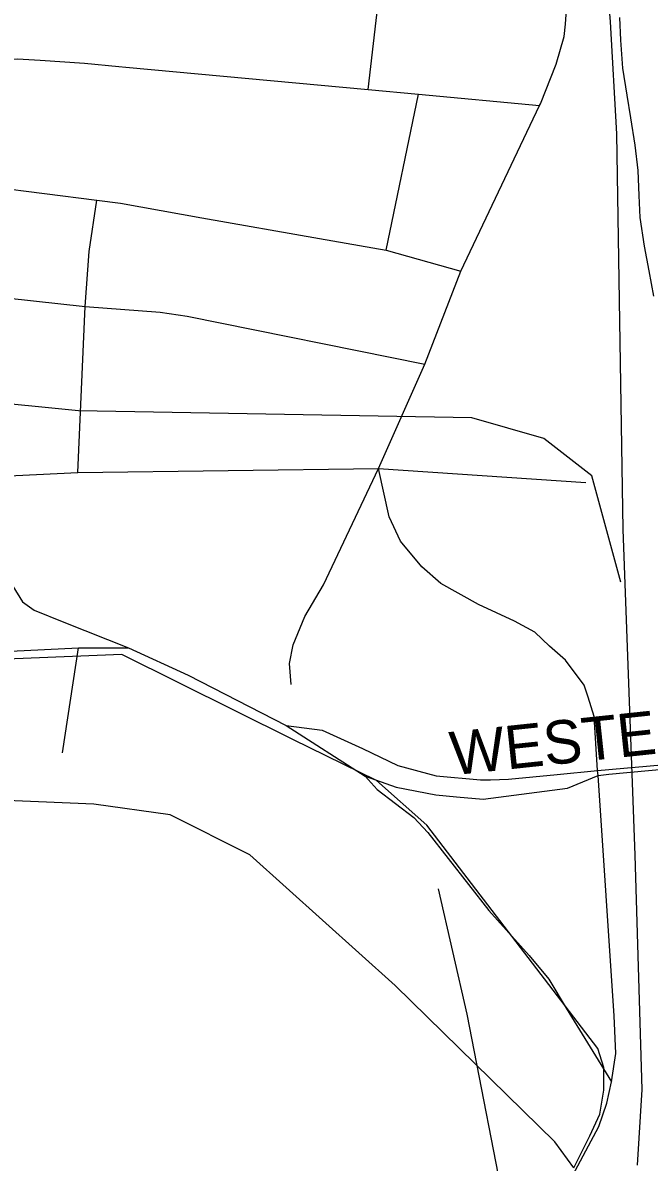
# Model space of a CAD drawing. Extents: x -8.2 to 38.5, y -0.1 to 21.9.
# Drawn here: x 5.1615 to 5.4346, y 15.5938 to 16.091 of the extents above; entities that cross this region are included whole.
import ezdxf

# ---------------------------------------------------------------- set-up
doc = ezdxf.new("R2010")
doc.units = 0
for name, color, linetype in [('GM_X_Major_Lake', 7, 'Continuous'), ('GM_X_Minor_River', 7, 'Continuous'), ('GM_X_Township_Subdivision_Text', 7, 'Continuous'), ('GM_X_Township_Text', 7, 'Continuous'), ('GM_X_US_Location', 7, 'Continuous')]:
    doc.layers.add(name, color=color, linetype=linetype)

msp = doc.modelspace()

# ---------------------------------------------------------------- linework, layer by layer
at = {"layer": 'GM_X_Minor_River'}
msp.add_lwpolyline([(5.42167, 16.09329), (5.42215, 16.0834), (5.42295, 16.07123), (5.42489, 16.0594), (5.42651, 16.04949), (5.42845, 16.03766), (5.42966, 16.02662), (5.43011, 16.01559), (5.4306, 16.00608), (5.43252, 15.9935), (5.43449, 15.98281), (5.43646, 15.97175)], dxfattribs=at)
at = {"layer": 'GM_X_Township_Subdivision_Text'}
for p, q in [((5.31215, 16.06186), (5.31772, 16.11078)), ((5.31993, 15.99183), (5.33406, 16.05983)), ((5.31655, 15.89649), (5.40697, 15.89045)), ((5.17882, 15.77245), (5.18572, 15.81826))]:
    msp.add_line(p, q, dxfattribs=at)
for points in [[(4.99245, 16.10244), (5.01831, 16.09032), (5.02882, 16.08584), (5.04124, 16.08207), (5.05714, 16.08011), (5.11356, 16.07434), (5.12607, 16.07361), (5.13747, 16.07405), (5.15915, 16.07534), (5.169, 16.07469), (5.18833, 16.07338), (5.20337, 16.07199)], [(5.20337, 16.07199), (5.20638, 16.07171), (5.31215, 16.06186), (5.33406, 16.05983), (5.38685, 16.05491)], [(4.96834, 16.04118), (5.00922, 16.03624), (5.03609, 16.03307), (5.10232, 16.02526), (5.19371, 16.01366), (5.20406, 16.01226), (5.21295, 16.01065)], [(5.18541, 15.89482), (5.18867, 15.9672), (5.19035, 15.99127), (5.19371, 16.01366)], [(5.21295, 16.01065), (5.23961, 16.00583), (5.2909, 15.99689)], [(4.88396, 15.99973), (4.90434, 15.99825), (4.95087, 15.99299), (5.02942, 15.98463), (5.18867, 15.9672), (5.22141, 15.96468), (5.23317, 15.963), (5.33673, 15.94201)], [(5.2909, 15.99689), (5.31993, 15.99183), (5.35249, 15.98255)], [(5.31071, 15.76226), (5.31604, 15.75643), (5.33202, 15.74425), (5.33811, 15.73766), (5.36475, 15.70366), (5.38234, 15.68398), (5.39087, 15.67368), (5.39842, 15.66103), (5.41823, 15.62878)], [(5.37804, 15.54442), (5.37314, 15.56648), (5.35521, 15.6584), (5.3428, 15.71309)]]:
    msp.add_lwpolyline(points, dxfattribs=at)
at = {"layer": 'GM_X_Township_Text'}
for points in [[(5.31655, 15.89649), (5.33673, 15.94201), (5.35249, 15.98255), (5.38685, 16.05491), (5.3872, 16.05564), (5.39413, 16.07292), (5.39751, 16.08498), (5.39816, 16.09042), (5.39951, 16.1096), (5.3939, 16.14664)], [(5.14022, 15.89257), (5.18541, 15.89482), (5.31655, 15.89649)], [(5.27855, 15.80229), (5.27774, 15.81146), (5.27936, 15.81955), (5.28448, 15.83195), (5.29257, 15.84569), (5.31655, 15.89649)], [(5.40797, 15.79668), (5.40633, 15.80194), (5.39813, 15.81287), (5.39114, 15.81895), (5.38476, 15.82503), (5.37595, 15.82989), (5.36016, 15.83718), (5.34375, 15.84629), (5.33555, 15.85358), (5.32613, 15.86482), (5.32127, 15.87545), (5.31655, 15.89649)], [(4.44755, 15.88801), (4.46835, 15.8839), (4.5292, 15.8681), (4.5955, 15.8513), (4.6311, 15.8463), (4.72978, 15.83462), (4.82189, 15.82572), (4.9015, 15.81619), (5.00354, 15.80537), (5.03602, 15.80133), (5.0574, 15.79844), (5.06468, 15.79913), (5.07012, 15.80052), (5.08986, 15.80977), (5.0977, 15.81213), (5.10681, 15.81378), (5.1411, 15.81602), (5.18572, 15.81826), (5.20756, 15.81819)], [(5.14022, 15.89257), (5.15298, 15.85486), (5.15715, 15.84508), (5.16132, 15.83831), (5.16646, 15.83473), (5.17936, 15.82951), (5.20756, 15.81819)], [(5.20756, 15.81819), (5.23365, 15.80626), (5.2763, 15.78435)], [(5.40025, 15.58593), (5.41264, 15.60936), (5.41617, 15.61956), (5.41823, 15.62878), (5.42009, 15.64113), (5.4193, 15.6576), (5.41243, 15.76247), (5.41217, 15.76468), (5.41058, 15.78827), (5.40797, 15.79668)], [(5.2763, 15.78435), (5.29199, 15.78237), (5.30967, 15.77427), (5.32503, 15.76684), (5.34172, 15.76238), (5.36105, 15.76056), (5.36548, 15.76069)], [(5.2763, 15.78435), (5.31071, 15.76226), (5.32424, 15.7574), (5.34159, 15.75406), (5.35058, 15.75327)], [(5.35058, 15.75327), (5.36227, 15.75224), (5.39896, 15.75698), (5.41243, 15.76247), (5.41702, 15.7631), (5.53825, 15.77434), (5.5921, 15.77927), (5.62445, 15.78144), (5.64616, 15.78124), (5.68235, 15.77949), (5.73877, 15.77176), (5.74901, 15.77008), (5.82828, 15.75708)], [(5.39447, 15.76297), (5.41217, 15.76468), (5.53864, 15.7759), (5.59173, 15.78026), (5.62535, 15.78248), (5.65622, 15.78248), (5.6871, 15.78092), (5.71063, 15.77811), (5.73505, 15.77479), (5.74946, 15.77294), (5.82847, 15.75936)], [(5.36548, 15.76069), (5.37323, 15.76092), (5.39447, 15.76297)]]:
    msp.add_lwpolyline(points, dxfattribs=at)
at = {"layer": 'GM_X_US_Location'}
for points in [[(5.42951, 15.59244), (5.43153, 15.62547), (5.42849, 15.72782), (5.42327, 15.86992), (5.42054, 16.04249), (5.41781, 16.0914), (5.4136, 16.14238), (5.40465, 16.1983), (5.38962, 16.26784), (5.3779, 16.31416), (5.36787, 16.34517), (5.34216, 16.41673), (5.3257, 16.45705), (5.31303, 16.48405), (5.29277, 16.52572), (5.25708, 16.59623), (5.23599, 16.64632), (5.20315, 16.73), (5.19578, 16.74801), (5.17214, 16.81878)], [(5.42231, 15.84691), (5.40957, 15.89323), (5.38868, 15.90966), (5.35734, 15.91863), (5.18572, 15.92162), (5.05141, 15.93506), (5.00067, 15.93954), (4.77234, 15.93654), (4.62609, 15.94997), (4.45448, 15.99924), (4.34704, 16.03956), (4.16199, 16.09481), (4.08887, 16.1172), (4.02918, 16.12019), (3.84612, 16.11588), (3.54158, 16.17911), (3.37065, 16.20444), (3.15964, 16.25091), (3.04991, 16.30793), (2.98497, 16.37271), (2.97481, 16.51211), (2.969, 16.6094), (2.95384, 16.66998)], [(5.40181, 15.59132), (5.39352, 15.60269), (5.32387, 15.67083), (5.26054, 15.72787), (5.22571, 15.7453), (5.19246, 15.75006), (5.11647, 15.75323), (4.86892, 15.76816), (4.73477, 15.78286), (4.67658, 15.78838), (4.42055, 15.85455), (4.33051, 15.88396), (4.23373, 15.91214), (4.14757, 15.93855), (4.06367, 15.97023)], [(5.40181, 15.59132), (5.40878, 15.60521), (5.41312, 15.61475), (5.41485, 15.62515), (5.41485, 15.63512), (5.41225, 15.64336), (5.33774, 15.74089), (5.31565, 15.7604), (5.27926, 15.77817), (5.2046, 15.81536), (5.10046, 15.81107), (5.07056, 15.80076), (4.73233, 15.83128), (4.59941, 15.84905), (4.44837, 15.88946)]]:
    msp.add_lwpolyline(points, dxfattribs=at)

# ---------------------------------------------------------------- texts
at = {"layer": 'GM_X_Major_Lake'}
msp.add_text('WESTERN', height=0.018939, rotation=6.0537, dxfattribs=at).set_placement((5.34887, 15.76259))

doc.saveas('drawing.dxf')
